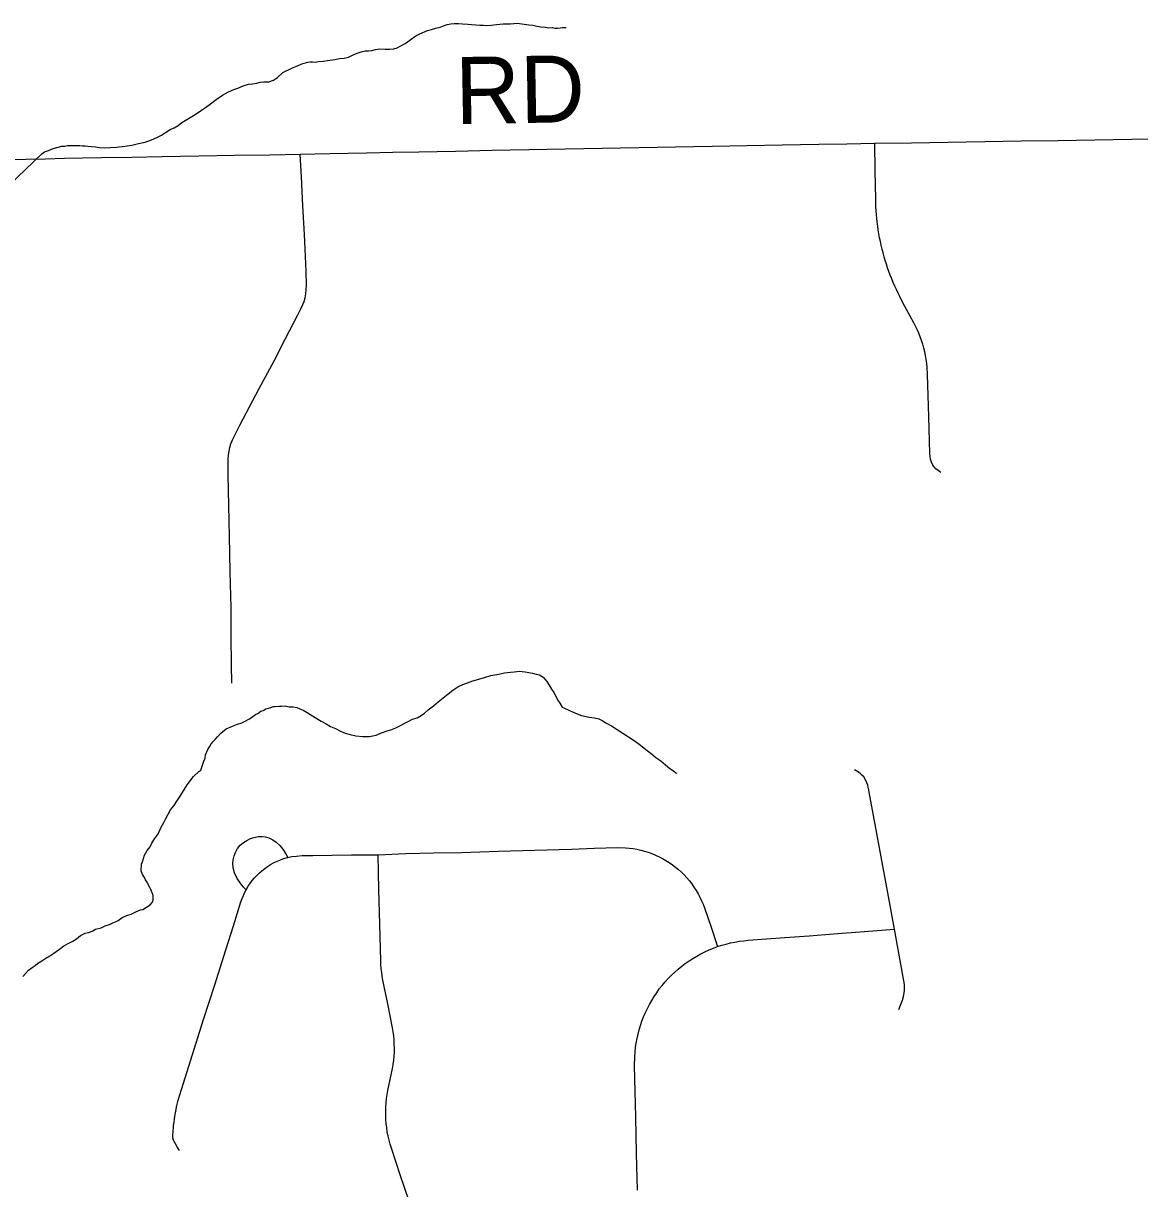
# Model space of a CAD drawing. Extents: x 103424 to 286016, y 38711 to 110967.
# Drawn here: x 109845 to 114869, y 58393 to 63637 of the extents above; entities that cross this region are included whole.
import ezdxf

# ---------------------------------------------------------------- set-up
doc = ezdxf.new("R2010")
doc.units = 0
for name, color, linetype in [('GM_X_Minor_River', 7, 'Continuous'), ('GM_X_Township_Road', 7, 'Continuous'), ('GM_X_Township_Road_Text', 7, 'Continuous')]:
    doc.layers.add(name, color=color, linetype=linetype)

msp = doc.modelspace()

# ---------------------------------------------------------------- linework, layer by layer
at = {"layer": 'GM_X_Minor_River'}
for points in [[(109780.6, 62908.2), (109927.4, 63050.2), (109939.4, 63058.4), (109957.5, 63064.8), (109979.5, 63073.2), (110017.7, 63084), (110031.8, 63084.2), (110043.9, 63086.4), (110064, 63086.7), (110082.2, 63087), (110098.3, 63087.3), (110110.5, 63085.5), (110122.6, 63085.7), (110134.7, 63083.9), (110150.9, 63082.1), (110169.1, 63080.4), (110187.3, 63078.7), (110209.5, 63077), (110235.7, 63077.4), (110263.9, 63079.9), (110302.2, 63084.6), (110332.4, 63089.1), (110362.5, 63095.7), (110392.7, 63102.2), (110420.8, 63112.8), (110444.8, 63123.3), (110466.8, 63133.8), (110484.8, 63146.2), (110504.8, 63158.6), (110522.8, 63167), (110540.8, 63177.4), (110558.7, 63189.8), (110618.6, 63227.2), (110642.6, 63243.7), (110664.5, 63258.2), (110686.4, 63274.8), (110712.4, 63293.4), (110740.3, 63314), (110768.3, 63328.6), (110792.3, 63339.1), (110810.4, 63345.5), (110834.4, 63356), (110858.5, 63362.4), (110876.6, 63364.8), (110894.8, 63367.1), (110910.8, 63371.4), (110924.9, 63373.6), (110939, 63373.9), (110949.1, 63374), (110971.2, 63380.5), (110989.2, 63392.9), (111013, 63415.5), (111053.1, 63434.3), (111081.1, 63446.9), (111103.2, 63455.4), (111115.2, 63459.6), (111125.2, 63461.8), (111135.3, 63464), (111145.4, 63464.1), (111157.5, 63462.3), (111173.6, 63464.6), (111193.8, 63467), (111213.9, 63469.3), (111246.1, 63473.9), (111268.2, 63478.3), (111288.4, 63480.6), (111308.5, 63485), (111326.5, 63493.4), (111346.5, 63501.8), (111364.6, 63508.1), (111382.7, 63512.5), (111398.8, 63512.8), (111412.9, 63515), (111429, 63519.3), (111447.1, 63521.6), (111473.4, 63520), (111493.5, 63520.4), (111511.7, 63522.7), (111527.7, 63527), (111543.7, 63535.3), (111563.7, 63545.8), (111611.6, 63580.9), (111629.6, 63589.3), (111639.6, 63593.5), (111653.6, 63599.8), (111663.7, 63604), (111681.7, 63608.3), (111701.8, 63614.7), (111719.9, 63619), (111735.9, 63625.4), (111752, 63631.7), (111768.1, 63634), (111784.2, 63636.3), (111802.4, 63636.6), (111820.5, 63634.8), (111844.8, 63633.2)], [(111844.8, 63633.2), (111861, 63631.5), (111881.2, 63629.8), (111899.4, 63628.1), (111915.5, 63628.3), (111929.6, 63626.5), (111949.8, 63628.9), (111974, 63631.3), (112004.2, 63633.8), (112036.5, 63634.4), (112066.7, 63636.9), (112099, 63633.4), (112119.3, 63629.7), (112137.5, 63627.9), (112155.7, 63624.2), (112173.9, 63620.5), (112194.1, 63618.8), (112210.3, 63617), (112226.4, 63617.3), (112236.6, 63615.4), (112250.7, 63615.6), (112270.8, 63618), (112284.9, 63618.2), (112287, 63618.3)], [(110495.9, 60077.6), (110507.6, 60097.9), (110521.4, 60116.4), (110535.2, 60136.8), (110553, 60163.3), (110582.4, 60210.3), (110610.1, 60247.1), (110633.9, 60269.7), (110643.9, 60276), (110651.6, 60298.3), (110657.3, 60316.6), (110663.1, 60330.8), (110664.9, 60345), (110674.6, 60369.4), (110682.5, 60381.6), (110688.4, 60391.8), (110698.2, 60404.1), (110708.2, 60414.4), (110718, 60426.7), (110733.9, 60443.1), (110757.8, 60461.7), (110785.9, 60474.3), (110807.9, 60482.7), (110828, 60489.1), (110840, 60495.3), (110862, 60507.8), (110877.9, 60518.2), (110889.9, 60526.5), (110899.9, 60530.7), (110913.9, 60541), (110923.9, 60545.2), (110935.9, 60551.5), (110947.9, 60555.7), (110958, 60557.9), (110970, 60562.1), (110980.1, 60562.3), (110994.2, 60564.6), (111006.3, 60564.8), (111022.5, 60565), (111040.7, 60561.3), (111058.8, 60561.6), (111075, 60557.8), (111089.3, 60552), (111103.5, 60546.1), (111121.8, 60536.4), (111138.2, 60524.5), (111158.5, 60512.7), (111185, 60497), (111207.4, 60485.2), (111227.8, 60473.4), (111250.2, 60463.7), (111272.6, 60452), (111292.9, 60442.2), (111315.2, 60436.5), (111341.5, 60430.9), (111371.9, 60427.3), (111402.1, 60427.8), (111432.3, 60434.4), (111456.3, 60444.9), (111482.4, 60453.4), (111502.5, 60459.8), (111520.5, 60466.1), (111576.5, 60495.3), (111596.5, 60505.8), (111616.6, 60512.2), (111634.6, 60522.6), (111650.6, 60532.9), (111666.5, 60547.3), (111690.4, 60565.9), (111712.3, 60584.4), (111734.2, 60601), (111756.1, 60619.5), (111778, 60636), (111799.9, 60650.5), (111822, 60661), (111844, 60669.4), (111868.1, 60677.9), (111894.2, 60686.4), (111920.3, 60692.9), (111948.4, 60701.5), (111984.6, 60708.1), (112010.7, 60714.6), (112036.9, 60717.1), (112053, 60719.3), (112065.1, 60719.6), (112077.2, 60721.8), (112089.3, 60719.9), (112103.5, 60718.2), (112119.7, 60716.4), (112135.9, 60712.6), (112152.1, 60708.9), (112168.3, 60705.1), (112184.6, 60695.3), (112201.1, 60675.3), (112211.4, 60659.3), (112221.8, 60641.3), (112232.2, 60625.3), (112240.5, 60609.3), (112248.9, 60593.3), (112259.2, 60577.3), (112269.6, 60559.3)], [(112269.6, 60559.3), (112296.1, 60547.6), (112322.5, 60535.9), (112357, 60522.3), (112391.4, 60514.8), (112415.7, 60511.2), (112433.9, 60507.4), (112450.2, 60499.6), (112466.5, 60489.8), (112491, 60476), (112593, 60409), (112621.6, 60389.3), (112646.1, 60369.5), (112670.6, 60351.7), (112691.1, 60333.9), (112713.6, 60318.1), (112734, 60300.2), (112754.5, 60284.4), (112770.8, 60272.6), (112781, 60264.6), (112785.1, 60262.7)], [(109842.2, 59347.6), (109854.1, 59361.9), (109867.9, 59376.3), (109883.9, 59388.7), (109897.9, 59397), (109909.8, 59407.3), (109927.8, 59417.7), (109945.7, 59430.1), (109963.7, 59440.5), (109981.7, 59452.9), (110007.6, 59471.5), (110027.5, 59486), (110049.5, 59498.5), (110067.5, 59506.9), (110083.5, 59517.2), (110101.4, 59531.6), (110123.5, 59542.1), (110139.5, 59546.4), (110157.6, 59552.8), (110169.6, 59561.1), (110195.7, 59567.5), (110213.7, 59575.9), (110231.8, 59582.3), (110247.8, 59588.6), (110261.8, 59594.9), (110271.8, 59599.1), (110289.8, 59613.5), (110309.8, 59622), (110329.9, 59628.3), (110341.9, 59634.6), (110353.9, 59640.9), (110371.9, 59647.2), (110382, 59649.4), (110415.9, 59670.2), (110425.8, 59682.4), (110429.7, 59692.6), (110429.3, 59712.8), (110425.1, 59724.9), (110418.8, 59738.9), (110414.6, 59748.9), (110408.4, 59758.9), (110402.1, 59773), (110393.9, 59782.9), (110389.7, 59793), (110381.4, 59807), (110375, 59823), (110376.5, 59853.4), (110380.4, 59863.5), (110390, 59894), (110401.7, 59914.4), (110415.6, 59930.8), (110423.4, 59947.1), (110435.2, 59967.5), (110449, 59985.9), (110456.8, 60002.2), (110462.6, 60014.4), (110470.4, 60030.7), (110476.3, 60040.9), (110486.1, 60059.2), (110495.9, 60077.6)]]:
    msp.add_lwpolyline(points, dxfattribs=at)
at = {"layer": 'GM_X_Township_Road'}
for points in [[(109692.7, 63023.2), (109857.7, 63026.2), (109944, 63027.8), (110030.2, 63029.4), (110195.2, 63032.5), (110332.5, 63035.1), (110469.8, 63037.7), (110634.8, 63040.4), (110794.6, 63043), (110954.3, 63045.7), (111091, 63047.9), (111224.6, 63050.7), (111389.6, 63054.2), (111507, 63056.6), (111624.4, 63059.1), (111789.5, 63062.2), (111954.5, 63065.3), (112119.5, 63068.3), (112284.6, 63071.4), (112449.6, 63074.5), (112614.6, 63077.6), (112779.7, 63080.7), (112944.7, 63083.8), (113102.1, 63086.7), (113259.4, 63089.7), (113424.4, 63092.6), (113550.4, 63094.8), (113676.2, 63097), (113841.3, 63099.7), (114006.3, 63102.3), (114171.3, 63104.9), (114336.4, 63107.6), (114501.4, 63110.2), (114666.4, 63112.8), (114831.5, 63115.4), (114996.5, 63118.1)], [(113973.7, 61615.8), (113962, 61624.3), (113952, 61632), (113944.3, 61640.5), (113938.1, 61648.2), (113931.8, 61661.8), (113927.8, 61675.4), (113925.9, 61687.5), (113924.7, 61701.8), (113919.4, 61866.8), (113916.4, 61961.4), (113913.3, 62056.1), (113911.8, 62089.1), (113910.1, 62106.6), (113907.8, 62124), (113905, 62141.4), (113901.5, 62158.5), (113897.3, 62175.7), (113892.5, 62192.6), (113887.2, 62209.3), (113881.4, 62225.9), (113874.9, 62242.3), (113867.8, 62258.4), (113860.3, 62274.1), (113852.3, 62289.8), (113803.2, 62379.6), (113788.9, 62407), (113781.1, 62422.8), (113773.6, 62438.7), (113766.3, 62454.7), (113759.5, 62470.8), (113752.7, 62487.1), (113746.4, 62503.4), (113740.1, 62520), (113734.3, 62536.5), (113728.8, 62553.2), (113723.5, 62570), (113718.7, 62586.8), (113714, 62603.8), (113709.7, 62620.8), (113705.7, 62637.9), (113701.9, 62655.1), (113698.4, 62672.3), (113695.4, 62689.6), (113692.3, 62706.9), (113689.8, 62724.3), (113687.6, 62741.7), (113685.8, 62759.2), (113684.1, 62776.7), (113682.8, 62794.2), (113681.8, 62811.8), (113681.1, 62829.4), (113680.6, 62846.9), (113678.4, 62972), (113676.2, 63097)], [(110783.2, 60667), (110781.6, 60750.6), (110780.5, 60878.9), (110779.5, 61007.2), (110776, 61168.4), (110772.4, 61329.7), (110769.6, 61466.7), (110766.8, 61603.7), (110766.3, 61645), (110766.8, 61674.7), (110768.4, 61694.4), (110770.8, 61711), (110774, 61727.7), (110779, 61744.4), (110787.7, 61765.2), (110818.6, 61828.3), (110862.4, 61910.8), (110906.2, 61993.3), (110973.5, 62118.5), (111022.3, 62215.3), (111080.7, 62325.7), (111093.7, 62351.9), (111102.2, 62371.1), (111108, 62385.4), (111112.5, 62401.9), (111115.6, 62420.2), (111117.4, 62437.7), (111118.7, 62458.7), (111117.7, 62521.7), (111109.3, 62686.6), (111102.8, 62816.1), (111096.2, 62945.6), (111091, 63047.9)], [(113784.6, 59199.9), (113791.9, 59218.3), (113801.5, 59241.5), (113805.6, 59258.4), (113809.8, 59283.1), (113810.4, 59311.3), (113787.6, 59436.3), (113764.6, 59561.3), (113734.8, 59723.7), (113705, 59886), (113678.3, 60031.6), (113651.6, 60177.2), (113649.7, 60187.7), (113646.9, 60200.4), (113644.7, 60208.6), (113641.4, 60219.7), (113633.6, 60235.4), (113626.7, 60245.6), (113618.8, 60253.8), (113611.6, 60260.4), (113603.9, 60266.6), (113585.9, 60278.1)], [(110847.4, 59737.6), (110834.7, 59751.5), (110819.9, 59769.3), (110806.7, 59788.7), (110795.6, 59813.9), (110789.4, 59836.4), (110787.5, 59856.9), (110789.6, 59873.3), (110793.3, 59891), (110799, 59906.5), (110808.9, 59924.4), (110820.7, 59938.4), (110835.1, 59950.1), (110849.8, 59959.7), (110866.6, 59968.1), (110884, 59973.3), (110901.9, 59977.2), (110919, 59978.2), (110933.7, 59976.1), (110950.1, 59971.6), (110966.9, 59962.8), (110982.6, 59952.7), (110999.1, 59938), (111013, 59920.3), (111025.6, 59899.5), (111035.1, 59884)], [(110547.1, 58565.4), (110537.5, 58581.2), (110529.4, 58595.2), (110524.2, 58605.3), (110521.2, 58611.3), (110518, 58621.3), (110517.3, 58631.9), (110519.8, 58668), (110521, 58677.9), (110522.9, 58692.9), (110525, 58708.1), (110526.4, 58717.6), (110530.9, 58742.2), (110536.2, 58766.7), (110542, 58791), (110548.6, 58815.1), (110555.9, 58839.1), (110605.9, 58996.4), (110655.8, 59153.7), (110705.8, 59311), (110755.8, 59468.3), (110789.9, 59575.9), (110824.1, 59683.5), (110829.4, 59698.2), (110835.2, 59712.7), (110841.8, 59726.9), (110847.4, 59737.6), (110857.1, 59754), (110865.7, 59766.9), (110875.2, 59779.4), (110885.1, 59791.4), (110895.6, 59802.8), (110907, 59813.7), (110918.6, 59824), (110930.9, 59833.7), (110943.5, 59842.7), (110956.6, 59851.1), (110970.2, 59858.8), (110984.3, 59865.7), (110998.6, 59871.9), (111013.2, 59877.4), (111028.1, 59882.1), (111035.1, 59884), (111053, 59887.4), (111074.6, 59889.9), (111099.5, 59891.6), (111147.5, 59892.6), (111234.6, 59893.7), (111321.6, 59894.9), (111440.9, 59895.7), (111566.1, 59900.7), (111691.2, 59903.6), (111816.4, 59906.5), (111981.4, 59911.5), (112146.4, 59916.5), (112311.4, 59921.4), (112415.2, 59924.6), (112519.1, 59927.7), (112554.3, 59927), (112571.7, 59925.6), (112589, 59923.3), (112606.4, 59920.3), (112623.5, 59916.5), (112640.4, 59912.1), (112657.3, 59906.8), (112673.6, 59900.8), (112690, 59894.2), (112705.8, 59886.8), (112721.4, 59878.7), (112736.8, 59870), (112751.4, 59860.7), (112766, 59850.7), (112779.8, 59840), (112793.4, 59828.7), (112806.2, 59816.9), (112818.8, 59804.6), (112830.6, 59791.7), (112842, 59778.3), (112852.8, 59764.4), (112862.8, 59750), (112872.4, 59735.3), (112881.2, 59720.2), (112889.2, 59704.6), (112896.8, 59688.7), (112903.6, 59672.6), (112909.6, 59656.1), (112939.5, 59569.2), (112969.4, 59482.4)], [(111580.4, 58336.6), (111540.7, 58456.1), (111501, 58575.5), (111495.5, 58593.5), (111490.4, 58611.6), (111486.1, 58630), (111482.6, 58648.5), (111479.9, 58667.1), (111477.6, 58685.8), (111476.1, 58704.5), (111475.4, 58723.4), (111476.1, 58761), (111477.4, 58779.8), (111479.4, 58798.5), (111482.2, 58817.1), (111485.8, 58835.6), (111505.9, 58934.3), (111509.2, 58952.4), (111512, 58970.6), (111513.7, 58988.9), (111515, 59007.3), (111514, 59062.6), (111512.3, 59081), (111509.8, 59099.2), (111506.5, 59117.3), (111484.9, 59224.5), (111463.3, 59331.6), (111460.1, 59348.9), (111457.6, 59366.3), (111455.5, 59383.8), (111454.3, 59401.3), (111453.5, 59418.8), (111449.2, 59583.8), (111445, 59739.8), (111440.9, 59895.7)], [(112608.7, 58386.4), (112604.9, 58551.4), (112601.1, 58716.5), (112598.5, 58830.9), (112595.9, 58945.4), (112596.4, 58986.6), (112597.7, 59007.1), (112599.9, 59027.6), (112603, 59047.9), (112606.5, 59068.2), (112611.1, 59088.3), (112616.3, 59108.2), (112622.2, 59127.9), (112628.7, 59147.3), (112636.3, 59166.6), (112644.3, 59185.5), (112653.2, 59204.1), (112662.5, 59222.4), (112672.5, 59240.3), (112683.4, 59257.8), (112695, 59274.9), (112706.8, 59291.6), (112719.6, 59307.8), (112732.8, 59323.5), (112746.6, 59338.7), (112761.2, 59353.4), (112776.1, 59367.6), (112791.4, 59381.2), (112807.5, 59394.2), (112823.9, 59406.6), (112840.8, 59418.4), (112857.9, 59429.5), (112875.8, 59440), (112893.7, 59449.8), (112912.3, 59459), (112930.9, 59467.5), (112950, 59475.2), (112969.4, 59482.4), (112988.6, 59488.5), (113007.9, 59494), (113027.3, 59498.8), (113047.2, 59502.9), (113067.1, 59506.3), (113087, 59508.9), (113107.2, 59510.8), (113271.8, 59522.9), (113381.6, 59531.1), (113491.4, 59539.2), (113628, 59550.2), (113764.6, 59561.3)]]:
    msp.add_lwpolyline(points, dxfattribs=at)

# ---------------------------------------------------------------- texts
at = {"layer": 'GM_X_Township_Road_Text'}
msp.add_text('RD', height=301.87, rotation=0.9872, dxfattribs=at).set_placement((111790.8, 63182.8))

doc.saveas('drawing.dxf')
